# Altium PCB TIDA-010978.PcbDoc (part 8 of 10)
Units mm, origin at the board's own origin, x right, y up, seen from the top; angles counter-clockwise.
Board outline 243.95 x 94.85 mm, 4 copper layers (Top Layer, Mid Layer 1, Mid Layer 2, Bottom Layer), stack 1.623 mm thick; 865 components, 374 nets, 2308 pads, 2132 vias.
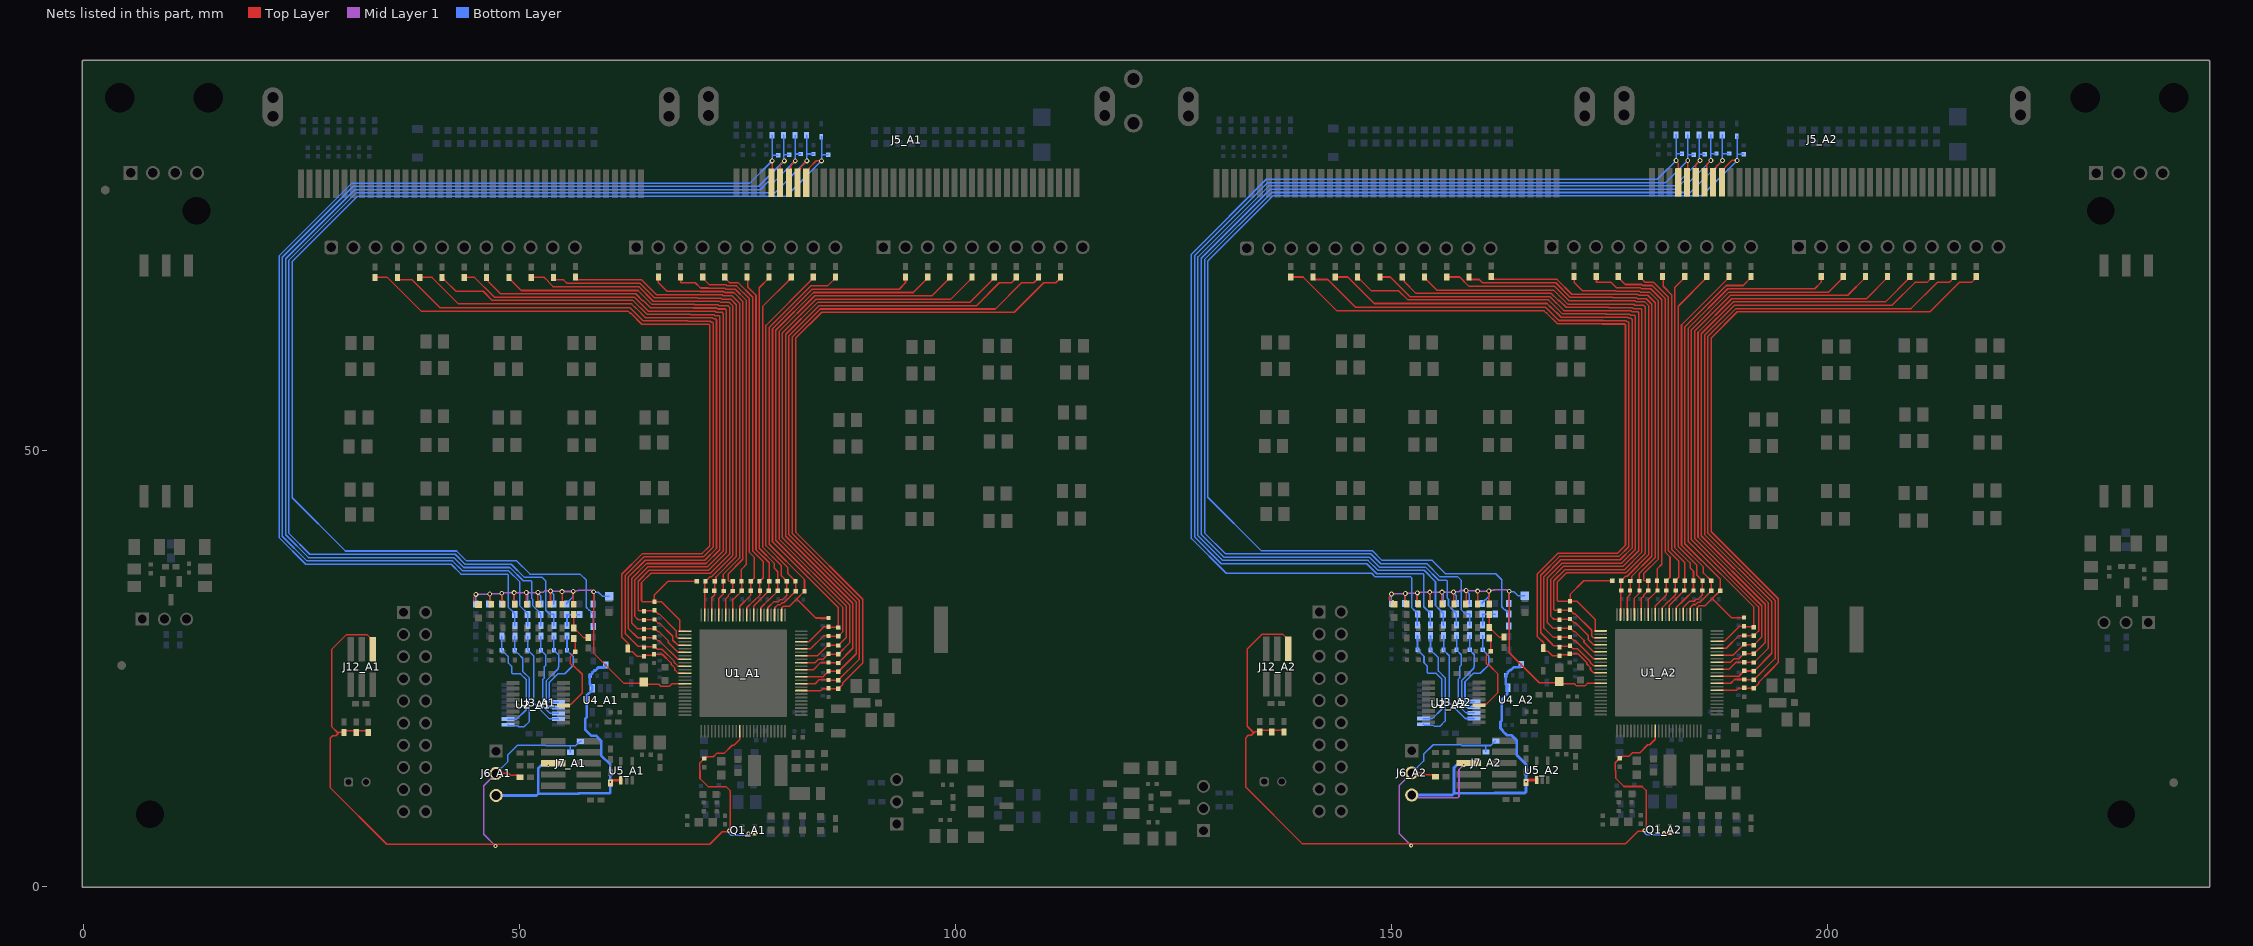
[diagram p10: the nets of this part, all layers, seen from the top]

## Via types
v1: diameter 0.559, hole 0.305, Top Layer to Bottom Layer, tented both sides, 1735 vias
v2: diameter 0.47, hole 0.2, Top Layer to Bottom Layer, tented both sides, 269 vias
v3: diameter 0.5, hole 0.2, Top Layer to Bottom Layer, tented both sides, 128 vias

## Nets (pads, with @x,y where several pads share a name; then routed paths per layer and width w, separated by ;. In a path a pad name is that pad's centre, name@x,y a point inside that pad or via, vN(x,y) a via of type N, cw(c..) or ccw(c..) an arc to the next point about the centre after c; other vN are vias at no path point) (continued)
TS10_A2: C78_A2.2 J5_A2.2 R137_A2.1 R143_A2.2 R144_A2.1 | length 131.7
  Top Layer w0.178: v1(182.649,83.25) 182.649,83.147 182.892,82.904 J5_A2.2@182.892,80.737
  Bottom Layer w0.178: R143_A2.2@152.984,29.951 152.974,29.962 R137_A2.1@152.974,31.221 152.974,31.321 152.562,31.732 152.554,31.732 152.348,31.938 152.348,35.361 152.223,35.486 148.142,35.486 147.727,35.901 131.047,35.901 127.053,39.895 127.053,72.501 135.633,81.081 137.767,81.081 180.48,81.081 v1(182.649,83.25) 182.649,84.012 ; R144_A2.1@182.624,86.187 182.649,86.162 182.649,84.012 ; C78_A2.2@183.317,84.012 182.649,84.012
TS10_MUX_A1: C65_A1.1 R143_A1.1 U2_A1.2 | length 12.7
  Bottom Layer w0.178: R143_A1.1@47.984,28.701 47.984,27.165 C65_A1.1@47.984,27.065 48.395,26.654 48.404,26.654 48.731,26.327 48.731,25.603 49.1,25.234 49.1,24.473 49.204,24.369 50.126,24.369 50.767,23.728 50.767,20.263 49.693,19.189 U2_A1.2@48.673,19.189
TS10_MUX_A2: C65_A2.1 R143_A2.1 U2_A2.2 | length 12.7
  Bottom Layer w0.178: R143_A2.1@152.984,28.751 152.984,27.215 C65_A2.1@152.984,27.115 153.395,26.704 153.404,26.704 153.731,26.377 153.731,25.653 154.1,25.284 154.1,24.523 154.204,24.419 155.126,24.419 155.767,23.778 155.767,20.313 154.693,19.239 U2_A2.2@153.673,19.239
TS11_A1: C84_A1.2 J5_A1.23 R135_A1.1 R149_A1.2 R150_A1.1 | length 133.7
  Top Layer w0.178: J5_A1.23@78.892,80.687 78.976,80.771 v1(78.976,83.2)
  Bottom Layer w0.178: R149_A1.2@49.477,29.901 49.462,29.917 R135_A1.1@49.462,31.171 49.462,31.271 49.051,31.682 49.042,31.682 48.699,32.025 48.699,35.71 48.595,35.814 43.299,35.814 42.165,36.947 25.486,36.947 22.431,40.002 22.431,72.295 30.79,80.654 32.767,80.654 76.429,80.654 v1(78.976,83.2) 78.976,83.862 ; R150_A1.1@78.951,86.137 78.976,86.112 78.976,83.862 ; C84_A1.2@79.667,83.862 78.976,83.862
TS11_A2: C84_A2.2 J5_A2.23 R135_A2.1 R149_A2.2 R150_A2.1 | length 133.7
  Top Layer w0.178: J5_A2.23@183.892,80.737 183.976,80.821 v1(183.976,83.25)
  Bottom Layer w0.178: R149_A2.2@154.477,29.951 154.462,29.967 R135_A2.1@154.462,31.221 154.462,31.321 154.051,31.732 154.042,31.732 153.699,32.075 153.699,35.76 153.595,35.864 148.299,35.864 147.165,36.997 130.486,36.997 127.431,40.052 127.431,72.345 135.79,80.704 137.767,80.704 181.429,80.704 v1(183.976,83.25) 183.976,83.912 ; R150_A2.1@183.951,86.187 183.976,86.162 183.976,83.912 ; C84_A2.2@184.667,83.912 183.976,83.912
TS11_MUX_A1: C63_A1.1 R149_A1.1 U2_A1.1 | length 13.3
  Bottom Layer w0.178: U2_A1.1@48.673,18.539 48.799,18.413 49.815,18.413 49.931,18.297 50.525,18.297 51.145,18.917 51.145,23.884 50.382,24.647 50.382,26.169 49.897,26.654 49.889,26.654 C63_A1.1@49.477,27.065 49.477,27.165 R149_A1.1@49.477,28.701
TS11_MUX_A2: C63_A2.1 R149_A2.1 U2_A2.1 | length 13.3
  Bottom Layer w0.178: U2_A2.1@153.673,18.589 153.799,18.463 154.815,18.463 154.931,18.347 155.525,18.347 156.145,18.967 156.145,23.934 155.382,24.697 155.382,26.219 154.897,26.704 154.889,26.704 C63_A2.1@154.477,27.115 154.477,27.215 R149_A2.1@154.477,28.751
TS12_A1: C86_A1.2 J5_A1.3 R133_A1.1 R156_A1.2 R157_A1.1 | length 135.2
  Top Layer w0.178: J5_A1.3@79.892,80.687 79.892,82.717 v1(80.376,83.2)
  Bottom Layer w0.178: R156_A1.2@50.971,29.901 50.95,29.922 R133_A1.1@50.95,31.171 50.95,31.271 50.539,31.682 50.53,31.682 50.051,32.162 50.051,34.893 48.752,36.192 43.455,36.192 42.322,37.325 25.642,37.325 22.809,40.158 22.809,72.138 30.946,80.276 32.767,80.276 77.451,80.276 v1(80.376,83.2) ; R157_A1.1@80.277,86.137 80.302,86.112 80.302,83.912 ; v1@80.303,83.201 80.303,83.912 C86_A1.2@80.942,83.912
TS12_A2: C86_A2.2 J5_A2.3 R133_A2.1 R156_A2.2 R157_A2.1 | length 135.2
  Top Layer w0.178: J5_A2.3@184.892,80.737 184.892,82.767 v1(185.376,83.25)
  Bottom Layer w0.178: R156_A2.2@155.971,29.951 155.95,29.972 R133_A2.1@155.95,31.221 155.95,31.321 155.539,31.732 155.53,31.732 155.051,32.212 155.051,34.943 153.752,36.242 148.455,36.242 147.322,37.375 130.642,37.375 127.809,40.208 127.809,72.188 135.946,80.326 137.767,80.326 182.451,80.326 v1(185.376,83.25) ; R157_A2.1@185.277,86.187 185.302,86.162 185.302,83.962 ; v1@185.303,83.251 185.303,83.962 C86_A2.2@185.942,83.962
TS12_MUX_A1: C61_A1.1 R156_A1.1 U2_A1.15 | length 11.6
  Bottom Layer w0.178: R156_A1.1@50.971,28.701 50.971,27.165 C61_A1.1@50.971,27.065 51.629,26.407 51.629,21.027 53.456,19.199 54.463,19.199 U2_A1.15@54.473,19.189
TS12_MUX_A2: C61_A2.1 R156_A2.1 U2_A2.15 | length 11.6
  Bottom Layer w0.178: R156_A2.1@155.971,28.751 155.971,27.215 C61_A2.1@155.971,27.115 156.629,26.457 156.629,21.077 158.456,19.249 159.463,19.249 U2_A2.15@159.473,19.239
TS13_A1: C89_A1.2 J5_A1.24 R132_A1.1 R159_A1.2 R160_A1.1 | length 137
  Top Layer w0.178: J5_A1.24@80.892,80.687 81.135,80.93 81.135,82.707 v1(81.629,83.2)
  Bottom Layer w0.178: R132_A1.1@52.438,31.171 52.438,29.927 R159_A1.2@52.464,29.901 ; R132_A1.1@52.438,31.271 52.027,31.682 52.018,31.682 51.539,32.162 51.539,32.891 51.402,33.027 51.402,34.951 51.298,35.055 50.423,35.055 48.908,36.569 43.612,36.569 42.478,37.703 25.799,37.703 23.187,40.315 23.187,71.982 31.103,79.898 32.767,79.898 77.608,79.898 78.483,80.773 79.201,80.773 v1(81.629,83.2) 81.629,83.987 ; R160_A1.1@81.603,86.137 81.629,86.112 81.629,83.987 ; C89_A1.2@82.267,83.987 81.629,83.987
TS13_A2: C89_A2.2 J5_A2.24 R132_A2.1 R159_A2.2 R160_A2.1 | length 137
  Top Layer w0.178: J5_A2.24@185.892,80.737 186.135,80.98 186.135,82.757 v1(186.629,83.25)
  Bottom Layer w0.178: R132_A2.1@157.438,31.221 157.438,29.977 R159_A2.2@157.464,29.951 ; R132_A2.1@157.438,31.321 157.027,31.732 157.018,31.732 156.539,32.212 156.539,32.941 156.402,33.077 156.402,35.001 156.298,35.105 155.423,35.105 153.908,36.619 148.612,36.619 147.478,37.753 130.799,37.753 128.187,40.365 128.187,72.032 136.103,79.948 137.767,79.948 182.608,79.948 183.483,80.823 184.201,80.823 v1(186.629,83.25) 186.629,84.037 ; R160_A2.1@186.603,86.187 186.629,86.162 186.629,84.037 ; C89_A2.2@187.267,84.037 186.629,84.037
TS13_MUX_A1: C60_A1.1 R159_A1.1 U2_A1.14 | length 10.5
  Bottom Layer w0.178: R159_A1.1@52.464,28.701 52.464,27.165 C60_A1.1@52.464,27.065 53.003,26.526 53.003,25.337 52.842,25.176 52.842,23.881 52.678,23.718 52.678,20.699 53.538,19.839 U2_A1.14@54.473,19.839
TS13_MUX_A2: C60_A2.1 R159_A2.1 U2_A2.14 | length 10.5
  Bottom Layer w0.178: R159_A2.1@157.464,28.751 157.464,27.215 C60_A2.1@157.464,27.115 158.003,26.576 158.003,25.387 157.842,25.226 157.842,23.931 157.678,23.768 157.678,20.749 158.538,19.889 U2_A2.14@159.473,19.889
TS14_A1: C92_A1.2 J5_A1.4 R131_A1.1 R163_A1.2 R164_A1.1 | length 139.7
  Top Layer w0.178: J5_A1.4@81.892,80.687 81.892,81.987 82.253,82.348 82.253,82.499 v1(82.955,83.2)
  Bottom Layer w0.178: R163_A1.2@53.958,29.901 53.958,31.113 54.015,31.171 R131_A1.1@53.926,31.171 53.878,31.219 53.463,31.219 53.027,31.656 53.027,33.61 52.993,33.643 52.993,34.114 53.027,34.147 53.027,35.029 52.623,35.433 50.579,35.433 49.065,36.947 43.768,36.947 42.635,38.081 25.955,38.081 23.565,40.471 23.565,71.826 31.259,79.52 79.275,79.52 v1(82.955,83.2) 82.955,83.987 ; R164_A1.1@82.93,86.137 82.955,86.112 82.955,83.987 ; C92_A1.2@83.717,83.987 82.955,83.987
TS14_A2: C92_A2.2 J5_A2.4 R131_A2.1 R163_A2.2 R164_A2.1 | length 139.7
  Top Layer w0.178: J5_A2.4@186.892,80.737 186.892,82.037 187.253,82.398 187.253,82.549 v1(187.955,83.25)
  Bottom Layer w0.178: R163_A2.2@158.958,29.951 158.958,31.163 159.015,31.221 R131_A2.1@158.926,31.221 158.878,31.269 158.463,31.269 158.027,31.706 158.027,33.66 157.993,33.693 157.993,34.164 158.027,34.197 158.027,35.079 157.623,35.483 155.579,35.483 154.065,36.997 148.768,36.997 147.635,38.131 130.955,38.131 128.565,40.521 128.565,71.876 136.259,79.57 184.275,79.57 v1(187.955,83.25) 187.955,84.037 ; R164_A2.1@187.93,86.187 187.955,86.162 187.955,84.037 ; C92_A2.2@188.717,84.037 187.955,84.037
TS14_MUX_A1: C59_A1.1 R163_A1.1 U2_A1.13 | length 10.2
  Bottom Layer w0.178: R163_A1.1@53.958,28.701 53.958,27.165 C59_A1.1@53.957,27.065 54.496,26.526 54.496,25.169 54.447,25.12 54.447,24.952 53.056,23.561 53.056,20.971 53.538,20.489 U2_A1.13@54.473,20.489
TS14_MUX_A2: C59_A2.1 R163_A2.1 U2_A2.13 | length 10.2
  Bottom Layer w0.178: R163_A2.1@158.958,28.751 158.958,27.215 C59_A2.1@158.957,27.115 159.496,26.576 159.496,25.219 159.447,25.17 159.447,25.002 158.056,23.611 158.056,21.021 158.538,20.539 U2_A2.13@159.473,20.539
TS15_A1: C118_A1.2 J5_A1.25 R193_A1.1 R196_A1.2 RT1_A1.1 | length 143
  Top Layer w0.178: J5_A1.25@82.892,80.687 82.892,81.987 83.253,82.348 83.253,82.428 84.026,83.2 v1(84.642,83.2)
  Bottom Layer w0.178: R196_A1.2@58.452,29.784 58.452,31.165 R193_A1.1@58.446,31.171 58.446,31.271 58.035,31.682 57.97,31.682 57.646,32.006 57.646,35.12 56.955,35.811 51.197,35.811 49.683,37.325 43.925,37.325 42.791,38.458 30.05,38.458 23.942,44.566 23.942,71.669 31.416,79.142 80.584,79.142 v1(84.642,83.2) 84.642,83.912 ; RT1_A1.1@84.617,85.972 84.642,85.947 84.642,83.912 ; C118_A1.2@85.392,83.912 84.642,83.912
TS15_A2: C118_A2.2 J5_A2.25 R193_A2.1 R196_A2.2 RT1_A2.1 | length 143
  Top Layer w0.178: J5_A2.25@187.892,80.737 187.892,82.037 188.253,82.398 188.253,82.478 189.026,83.25 v1(189.642,83.25)
  Bottom Layer w0.178: R196_A2.2@163.452,29.834 163.452,31.215 R193_A2.1@163.446,31.221 163.446,31.321 163.035,31.732 162.97,31.732 162.646,32.056 162.646,35.17 161.955,35.861 156.197,35.861 154.683,37.375 148.925,37.375 147.791,38.508 135.05,38.508 128.942,44.616 128.942,71.719 136.416,79.192 185.584,79.192 v1(189.642,83.25) 189.642,83.962 ; RT1_A2.1@189.617,86.022 189.642,85.997 189.642,83.962 ; C118_A2.2@190.392,83.962 189.642,83.962
TS_R1_A1: R171_A1.1 R184_A1.2 R185_A1.2 | length 3.7
  Top Layer w0.178: R171_A1.1@56.218,31.153 R184_A1.2@56.218,29.651 56.218,29.551 56.429,29.34 56.529,29.34 57.335,28.534 R185_A1.2@57.902,28.534
TS_R1_A2: R171_A2.1 R184_A2.2 R185_A2.2 | length 3.7
  Top Layer w0.178: R171_A2.1@161.218,31.203 R184_A2.2@161.218,29.701 161.218,29.601 161.429,29.39 161.529,29.39 162.335,28.584 R185_A2.2@162.902,28.584
TS_R1MUX_A1: C73_A1.1 R184_A1.1 U3_A1.12 | length 10
  Top Layer w0.178: U3_A1.12@55.043,20.724 55.179,20.86 55.884,20.86 57.202,22.178 57.202,24.319 56.207,25.314 56.058,25.314 55.849,25.524 55.849,26.355 C73_A1.1@56.387,26.893 56.387,28.282 R184_A1.1@56.218,28.451
TS_R1MUX_A2: C73_A2.1 R184_A2.1 U3_A2.12 | length 10
  Top Layer w0.178: U3_A2.12@160.043,20.774 160.179,20.91 160.884,20.91 162.202,22.228 162.202,24.369 161.207,25.364 161.058,25.364 160.849,25.574 160.849,26.405 C73_A2.1@161.387,26.943 161.387,28.332 R184_A2.1@161.218,28.501
TS_R2_A1: R134_A1.1 R152_A1.2 R153_A1.2 | length 2.8
  Bottom Layer w0.178: R152_A1.2@55.451,29.901 55.451,31.134 R134_A1.1@55.414,31.171 R153_A1.2@56.902,31.171
TS_R2_A2: R134_A2.1 R152_A2.2 R153_A2.2 | length 2.8
  Bottom Layer w0.178: R152_A2.2@160.451,29.951 160.451,31.184 R134_A2.1@160.414,31.221 R153_A2.2@161.902,31.221
TS_R2MUX_A1: C62_A1.1 R152_A1.1 U2_A1.12 | length 10.4
  Bottom Layer w0.178: U2_A1.12@54.473,21.139 53.538,21.139 53.434,21.243 53.434,23.405 54.408,24.379 55.188,24.379 56.175,25.366 56.175,26.349 55.871,26.654 55.862,26.654 C62_A1.1@55.451,27.065 55.451,27.165 R152_A1.1@55.451,28.701
TS_R2MUX_A2: C62_A2.1 R152_A2.1 U2_A2.12 | length 10.4
  Bottom Layer w0.178: U2_A2.12@159.473,21.189 158.538,21.189 158.434,21.293 158.434,23.455 159.408,24.429 160.188,24.429 161.175,25.416 161.175,26.399 160.871,26.704 160.862,26.704 C62_A2.1@160.451,27.115 160.451,27.215 R152_A2.1@160.451,28.751
TSREF_A1: C23_A1.2 C24_A1.2 R127_A1.1 R131_A1.2 R132_A1.2 R133_A1.2 R134_A1.2 R135_A1.2 R136_A1.2 R137_A1.2 R138_A1.2 R168_A1.2 R169_A1.2 R170_A1.2 R171_A1.2 R172_A1.2 R173_A1.2 R174_A1.2 R175_A1.2 R193_A1.2 U1_A1.66 | length 60.4
  Top Layer w0.178: v1(44.997,33.484) 44.997,33.381 44.733,33.117 44.733,32.865 45.246,32.353 C24_A1.2@45.296,32.353 ; v1(46.599,33.531) 46.599,32.513 R173_A1.2@46.759,32.353 ; v1(47.974,33.609) 47.974,32.489 R175_A1.2@48.11,32.353 ; v1(49.39,33.689) 49.39,32.424 R174_A1.2@49.462,32.353 ; v1(50.787,33.696) 50.787,32.379 R172_A1.2@50.813,32.353 ; v1(52.119,33.714) 52.119,32.398 R170_A1.2@52.164,32.353 ; R169_A1.2@53.515,32.353 53.562,32.399 v1(53.562,33.879) ; R168_A1.2@54.867,32.353 54.883,32.369 v1(54.883,33.804) ; v1(56.175,33.829) 56.175,32.396 R171_A1.2@56.218,32.353 ; v1(58.502,33.788) 58.502,26.755 61.943,23.314 64.124,23.314 C23_A1.2@64.246,23.436 64.488,23.194 65.961,23.194 66.215,22.94 67.193,22.94 67.49,23.237 68.971,23.237 U1_A1.66@68.982,23.249
  Mid Layer 1 w0.178: v1(44.997,33.484) 45.021,33.508 46.575,33.508 46.638,33.57 47.935,33.57 v1(47.974,33.609) 48.026,33.661 52.066,33.661 v1(52.119,33.714) 52.722,33.714 52.886,33.879 v1(53.562,33.879) 53.599,33.841 54.846,33.841 v1(54.883,33.804) 54.896,33.817 v1@56.162,33.817 ; v1@56.229,33.883 56.721,33.883 56.794,33.956 58.23,33.956 58.398,33.788 v1(58.502,33.788)
  Bottom Layer w0.178: v1(44.997,33.484) 44.997,32.402 R136_A1.2@45.066,32.333 ; R138_A1.2@46.486,32.371 46.599,32.484 v1(46.599,33.531) ; R137_A1.2@47.974,32.371 v1(47.974,33.609) ; v1(49.39,33.689) 49.39,32.442 R135_A1.2@49.462,32.371 ; v1(50.787,33.696) 50.787,33.593 50.95,33.43 R133_A1.2@50.95,32.371 ; v1(52.119,33.714) 52.119,33.611 52.438,33.292 R132_A1.2@52.438,32.371 ; v1(53.562,33.879) 53.562,33.834 53.926,33.47 R131_A1.2@53.926,32.371 ; R134_A1.2@55.414,32.371 55.414,32.471 56.175,33.232 v1(56.175,33.829) ; R193_A1.2@58.446,32.371 58.502,32.427 v1(58.502,33.788) 58.552,33.737 59.048,33.737 59.514,33.271 R127_A1.1@60.292,33.271
TSREF_A2: C23_A2.2 C24_A2.2 R127_A2.1 R131_A2.2 R132_A2.2 R133_A2.2 R134_A2.2 R135_A2.2 R136_A2.2 R137_A2.2 R138_A2.2 R168_A2.2 R169_A2.2 R170_A2.2 R171_A2.2 R172_A2.2 R173_A2.2 R174_A2.2 R175_A2.2 R193_A2.2 U1_A2.66 | length 60.4
  Top Layer w0.178: v1(149.997,33.534) 149.997,33.431 149.733,33.167 149.733,32.915 150.246,32.403 C24_A2.2@150.296,32.403 ; v1(151.599,33.581) 151.599,32.563 R173_A2.2@151.759,32.403 ; v1(152.974,33.659) 152.974,32.539 R175_A2.2@153.11,32.403 ; v1(154.39,33.739) 154.39,32.474 R174_A2.2@154.462,32.403 ; v1(155.787,33.746) 155.787,32.429 R172_A2.2@155.813,32.403 ; v1(157.119,33.764) 157.119,32.448 R170_A2.2@157.164,32.403 ; R169_A2.2@158.515,32.403 158.562,32.449 v1(158.562,33.929) ; R168_A2.2@159.867,32.403 159.883,32.419 v1(159.883,33.854) ; v1(161.175,33.879) 161.175,32.446 R171_A2.2@161.218,32.403 ; v1(163.502,33.838) 163.502,26.805 166.943,23.364 169.124,23.364 C23_A2.2@169.246,23.486 169.488,23.244 170.961,23.244 171.215,22.99 172.193,22.99 172.49,23.287 173.971,23.287 U1_A2.66@173.982,23.299
  Mid Layer 1 w0.178: v1(149.997,33.534) 150.021,33.558 151.575,33.558 151.638,33.62 152.935,33.62 v1(152.974,33.659) 153.026,33.711 157.066,33.711 v1(157.119,33.764) 157.722,33.764 157.886,33.929 v1(158.562,33.929) 158.599,33.891 159.846,33.891 v1(159.883,33.854) 159.896,33.867 v1@161.162,33.867 ; v1@161.229,33.933 161.721,33.933 161.794,34.006 163.23,34.006 163.398,33.838 v1(163.502,33.838)
  Bottom Layer w0.178: v1(149.997,33.534) 149.997,32.452 R136_A2.2@150.066,32.383 ; R138_A2.2@151.486,32.421 151.599,32.534 v1(151.599,33.581) ; R137_A2.2@152.974,32.421 v1(152.974,33.659) ; v1(154.39,33.739) 154.39,32.492 R135_A2.2@154.462,32.421 ; v1(155.787,33.746) 155.787,33.643 155.95,33.48 R133_A2.2@155.95,32.421 ; v1(157.119,33.764) 157.119,33.661 157.438,33.342 R132_A2.2@157.438,32.421 ; v1(158.562,33.929) 158.562,33.884 158.926,33.52 R131_A2.2@158.926,32.421 ; R134_A2.2@160.414,32.421 160.414,32.521 161.175,33.282 v1(161.175,33.879) ; R193_A2.2@163.446,32.421 163.502,32.477 v1(163.502,33.838) 163.552,33.787 164.048,33.787 164.514,33.321 R127_A2.1@165.292,33.321
VC0_A1: C162_A1.1 C164_A1.2 D8_A1.1 R231_A1.2 U1_A1.63 | length 94.4
  Top Layer w0.178: R231_A1.2@33.445,69.832 34.858,69.832 38.753,65.937 62.492,65.937 62.717,65.712 62.789,65.712 64.037,64.464 69.132,64.464 69.157,64.439 71.734,64.439 71.838,64.335 71.838,39.067 70.931,38.161 64.111,38.161 61.73,35.78 61.73,28.612 62.457,27.886 62.457,27.309 D8_A1.1@62.422,27.274 62.422,27.087 62.583,26.926 62.938,26.926 63.474,26.39 C162_A1.1@64.275,26.39 ; C162_A1.1@64.365,26.481 64.391,26.506 65.321,26.506 C164_A1.2@65.437,26.623 66.389,26.623 67.393,25.618 67.393,25.47 67.823,25.04 67.823,24.803 68.167,24.46 68.971,24.46 U1_A1.63@68.982,24.449
VC0_A2: C162_A2.1 C164_A2.2 D8_A2.1 R231_A2.2 U1_A2.63 | length 94.4
  Top Layer w0.178: R231_A2.2@138.445,69.882 139.858,69.882 143.753,65.987 167.492,65.987 167.717,65.762 167.789,65.762 169.037,64.514 174.132,64.514 174.157,64.489 176.734,64.489 176.838,64.385 176.838,39.117 175.931,38.211 169.111,38.211 166.73,35.83 166.73,28.662 167.457,27.936 167.457,27.359 D8_A2.1@167.422,27.324 167.422,27.137 167.583,26.976 167.938,26.976 168.474,26.44 C162_A2.1@169.275,26.44 ; C162_A2.1@169.365,26.531 169.391,26.556 170.321,26.556 C164_A2.2@170.437,26.673 171.389,26.673 172.393,25.668 172.393,25.52 172.823,25.09 172.823,24.853 173.167,24.51 173.971,24.51 U1_A2.63@173.982,24.499
VC1_A1: C156_A1.1 C162_A1.2 R229_A1.2 U1_A1.61 | length 91.1
  Top Layer w0.178: R229_A1.2@36.003,69.832 36.003,69.732 36.189,69.546 37.702,69.546 40.882,66.366 62.67,66.366 64.194,64.842 69.289,64.842 69.314,64.817 71.89,64.817 72.004,64.703 72.111,64.703 72.216,64.599 72.216,38.91 71.088,37.783 64.267,37.783 62.108,35.624 62.108,29.028 62.738,28.399 62.745,28.399 63.374,27.77 63.374,27.762 63.587,27.55 64.115,27.55 C162_A1.2@64.275,27.39 64.356,27.472 C156_A1.1@65.398,27.472 ; U1_A1.61@68.982,25.249 68.971,25.26 68.167,25.26 67.771,25.656 67.771,25.775 66.369,27.177 65.856,27.177 C156_A1.1@65.48,27.554 ; C156_A1.1@65.398,27.472 C156_A1.1@65.48,27.554 ; C156_A1.1@65.398,27.472 C156_A1.1@65.48,27.554 ; C156_A1.1@65.398,27.472 C156_A1.1@65.48,27.554
VC1_A2: C156_A2.1 C162_A2.2 R229_A2.2 U1_A2.61 | length 91.1
  Top Layer w0.178: R229_A2.2@141.003,69.882 141.003,69.782 141.189,69.596 142.702,69.596 145.882,66.416 167.67,66.416 169.194,64.892 174.289,64.892 174.314,64.867 176.89,64.867 177.004,64.753 177.111,64.753 177.216,64.649 177.216,38.96 176.088,37.833 169.267,37.833 167.108,35.674 167.108,29.078 167.738,28.449 167.745,28.449 168.374,27.82 168.374,27.812 168.587,27.6 169.115,27.6 C162_A2.2@169.275,27.44 169.356,27.522 C156_A2.1@170.398,27.522 ; U1_A2.61@173.982,25.299 173.971,25.31 173.167,25.31 172.771,25.706 172.771,25.825 171.369,27.227 170.856,27.227 C156_A2.1@170.48,27.604 ; C156_A2.1@170.398,27.522 C156_A2.1@170.48,27.604 ; C156_A2.1@170.398,27.522 C156_A2.1@170.48,27.604 ; C156_A2.1@170.398,27.522 C156_A2.1@170.48,27.604
VC2_A1: C152_A1.1 C156_A1.2 R223_A1.2 U1_A1.59 | length 87.6
  Top Layer w0.178: R223_A1.2@38.56,69.832 39.974,69.832 43.011,66.794 62.847,66.794 63.323,66.318 63.359,66.318 64.458,65.22 69.445,65.22 69.47,65.195 72.151,65.195 72.265,65.081 72.489,65.081 72.593,64.977 72.593,38.754 71.244,37.405 64.424,37.405 62.486,35.467 62.486,29.582 63.569,28.499 64.305,28.499 64.317,28.511 65.437,28.511 C156_A1.2@65.48,28.554 65.889,28.144 66.073,28.144 68.168,26.049 U1_A1.59@68.982,26.049
VC2_A2: C152_A2.1 C156_A2.2 R223_A2.2 U1_A2.59 | length 87.6
  Top Layer w0.178: R223_A2.2@143.56,69.882 144.974,69.882 148.011,66.844 167.847,66.844 168.323,66.368 168.359,66.368 169.458,65.27 174.445,65.27 174.47,65.245 177.151,65.245 177.265,65.131 177.489,65.131 177.593,65.027 177.593,38.804 176.244,37.455 169.424,37.455 167.486,35.517 167.486,29.632 168.569,28.549 169.305,28.549 169.317,28.561 170.437,28.561 C156_A2.2@170.48,28.604 170.889,28.194 171.073,28.194 173.168,26.099 U1_A2.59@173.982,26.099
VC3_A1: C144_A1.1 C152_A1.2 R219_A1.2 U1_A1.57 | length 84.8
  Top Layer w0.178: R219_A1.2@41.118,69.832 41.118,69.732 41.304,69.546 41.404,69.546 42.713,68.237 45.843,68.237 46.883,67.197 63.014,67.197 64.614,65.597 69.602,65.597 69.627,65.572 72.307,65.572 72.421,65.459 72.867,65.459 72.971,65.354 72.971,38.597 71.401,37.027 64.58,37.027 62.864,35.311 62.864,30.205 63.531,29.538 65.41,29.538 C144_A1.1@65.48,29.607 65.912,29.174 66.05,29.174 67.08,28.144 67.08,27.946 68.167,26.86 68.971,26.86 U1_A1.57@68.982,26.849
VC3_A2: C144_A2.1 C152_A2.2 R219_A2.2 U1_A2.57 | length 84.8
  Top Layer w0.178: R219_A2.2@146.118,69.882 146.118,69.782 146.304,69.596 146.404,69.596 147.713,68.287 150.843,68.287 151.883,67.247 168.014,67.247 169.614,65.647 174.602,65.647 174.627,65.622 177.307,65.622 177.421,65.509 177.867,65.509 177.971,65.404 177.971,38.647 176.401,37.077 169.58,37.077 167.864,35.361 167.864,30.255 168.531,29.588 170.41,29.588 C144_A2.1@170.48,29.657 170.912,29.224 171.05,29.224 172.08,28.194 172.08,27.996 173.167,26.91 173.971,26.91 U1_A2.57@173.982,26.899
VC4_A1: C136_A1.1 C144_A1.2 R216_A1.2 U1_A1.55 | length 81.7
  Top Layer w0.178: R216_A1.2@43.676,69.832 44.854,69.832 47.111,67.575 63.171,67.575 64.771,65.975 69.758,65.975 69.783,65.95 72.464,65.95 72.578,65.836 73.245,65.836 73.349,65.732 73.349,38.441 71.557,36.649 64.737,36.649 63.242,35.154 63.242,30.952 63.617,30.577 65.449,30.577 C144_A1.2@65.48,30.607 65.89,30.197 66.072,30.197 67.59,28.678 67.59,28.236 68.167,27.66 68.971,27.66 U1_A1.55@68.982,27.649
VC4_A2: C136_A2.1 C144_A2.2 R216_A2.2 U1_A2.55 | length 81.7
  Top Layer w0.178: R216_A2.2@148.676,69.882 149.854,69.882 152.111,67.625 168.171,67.625 169.771,66.025 174.758,66.025 174.783,66 177.464,66 177.578,65.886 178.245,65.886 178.349,65.782 178.349,38.491 176.557,36.699 169.737,36.699 168.242,35.204 168.242,31.002 168.617,30.627 170.449,30.627 C144_A2.2@170.48,30.657 170.89,30.247 171.072,30.247 172.59,28.728 172.59,28.286 173.167,27.71 173.971,27.71 U1_A2.55@173.982,27.699
VC5_A1: C130_A1.1 C136_A1.2 R213_A1.2 U1_A1.53 | length 78.9
  Top Layer w0.178: R213_A1.2@46.233,69.832 46.444,69.621 46.444,69.333 47.824,67.953 63.327,67.953 64.143,67.138 64.252,67.138 65.037,66.353 69.915,66.353 69.94,66.328 72.62,66.328 72.734,66.214 73.623,66.214 73.727,66.11 73.727,38.284 71.714,36.272 64.893,36.272 63.619,34.998 63.619,31.707 63.724,31.603 65.423,31.603 C130_A1.1@65.48,31.66 65.912,31.228 66.05,31.228 67.957,29.32 67.957,29.048 67.968,29.038 67.968,28.658 68.167,28.46 68.971,28.46 U1_A1.53@68.982,28.449
VC5_A2: C130_A2.1 C136_A2.2 R213_A2.2 U1_A2.53 | length 78.9
  Top Layer w0.178: R213_A2.2@151.233,69.882 151.444,69.671 151.444,69.383 152.824,68.003 168.327,68.003 169.143,67.188 169.252,67.188 170.037,66.403 174.915,66.403 174.94,66.378 177.62,66.378 177.734,66.264 178.623,66.264 178.727,66.16 178.727,38.334 176.714,36.322 169.893,36.322 168.619,35.048 168.619,31.757 168.724,31.653 170.423,31.653 C130_A2.1@170.48,31.71 170.912,31.278 171.05,31.278 172.957,29.37 172.957,29.098 172.968,29.088 172.968,28.708 173.167,28.51 173.971,28.51 U1_A2.53@173.982,28.499
VC6_A1: C126_A1.1 C130_A1.2 R207_A1.2 U1_A1.51 | length 82.1
  Top Layer w0.178: R207_A1.2@48.791,69.832 48.791,69.732 50.192,68.331 63.593,68.331 65.193,66.731 70.071,66.731 70.096,66.706 72.777,66.706 72.891,66.592 73.91,66.592 74.105,66.397 74.105,38.128 71.87,35.894 65.05,35.894 63.997,34.841 63.997,32.764 64.101,32.66 C130_A1.2@65.48,32.66 ; U1_A1.51@68.982,29.249 68.381,29.249 68.37,29.26 68.37,30.562 66.271,32.66 C130_A1.2@65.48,32.66 ; C126_A1.1@70.333,34.999 67.048,34.999 65.48,33.431 C130_A1.2@65.48,32.66
VC6_A2: C126_A2.1 C130_A2.2 R207_A2.2 U1_A2.51 | length 82.1
  Top Layer w0.178: R207_A2.2@153.791,69.882 153.791,69.782 155.192,68.381 168.593,68.381 170.193,66.781 175.071,66.781 175.096,66.756 177.777,66.756 177.891,66.642 178.91,66.642 179.105,66.447 179.105,38.178 176.87,35.944 170.05,35.944 168.997,34.891 168.997,32.814 169.101,32.71 C130_A2.2@170.48,32.71 ; U1_A2.51@173.982,29.299 173.381,29.299 173.37,29.31 173.37,30.612 171.271,32.71 C130_A2.2@170.48,32.71 ; C126_A2.1@175.333,35.049 172.048,35.049 170.48,33.481 C130_A2.2@170.48,32.71
VC7_A1: C120_A1.1 C126_A1.2 R205_A1.2 U1_A1.49 | length 61.4
  Top Layer w0.178: R205_A1.2@51.348,69.832 52.842,69.832 53.317,69.357 53.317,69.312 53.843,68.786 63.672,68.786 65.35,67.109 70.228,67.109 70.253,67.084 72.933,67.084 73.047,66.97 74.066,66.97 74.482,66.553 74.482,37.971 72.027,35.516 71.85,35.516 C126_A1.2@71.333,34.999 71.268,34.934 71.268,31.135 U1_A1.49@71.257,31.124
VC7_A2: C120_A2.1 C126_A2.2 R205_A2.2 U1_A2.49 | length 61.4
  Top Layer w0.178: R205_A2.2@156.348,69.882 157.842,69.882 158.317,69.407 158.317,69.362 158.843,68.836 168.672,68.836 170.35,67.159 175.228,67.159 175.253,67.134 177.933,67.134 178.047,67.02 179.066,67.02 179.482,66.603 179.482,38.021 177.027,35.566 176.85,35.566 C126_A2.2@176.333,35.049 176.268,34.984 176.268,31.185 U1_A2.49@176.257,31.174
VC8_A1: C116_A1.1 C120_A1.2 R203_A1.2 U1_A1.47 | length 59.1
  Top Layer w0.178: R203_A1.2@53.906,69.832 53.906,69.732 54.091,69.546 55.058,69.546 55.441,69.164 63.829,69.164 65.506,67.486 70.384,67.486 70.409,67.461 73.09,67.461 73.204,67.348 74.223,67.348 74.86,66.71 74.86,37.815 72.536,35.491 72.536,35.117 C116_A1.1@72.394,34.974 72.394,33.449 72.057,33.112 U1_A1.47@72.057,31.124
VC8_A2: C116_A2.1 C120_A2.2 R203_A2.2 U1_A2.47 | length 59.1
  Top Layer w0.178: R203_A2.2@158.906,69.882 158.906,69.782 159.091,69.596 160.058,69.596 160.441,69.214 168.829,69.214 170.506,67.536 175.384,67.536 175.409,67.511 178.09,67.511 178.204,67.398 179.223,67.398 179.86,66.76 179.86,37.865 177.536,35.541 177.536,35.167 C116_A2.1@177.394,35.024 177.394,33.499 177.057,33.162 U1_A2.47@177.057,31.174
VC9_A1: C110_A1.1 C116_A1.2 R201_A1.2 U1_A1.45 | length 56.8
  Top Layer w0.178: R201_A1.2@56.438,69.867 56.438,69.767 56.649,69.556 63.991,69.556 65.683,67.864 70.541,67.864 70.566,67.839 73.246,67.839 73.36,67.725 74.379,67.725 75.238,66.866 75.238,37.658 73.394,35.815 C116_A1.2@73.394,34.974 73.394,33.549 72.857,33.012 U1_A1.45@72.857,31.124
VC9_A2: C110_A2.1 C116_A2.2 R201_A2.2 U1_A2.45 | length 56.8
  Top Layer w0.178: R201_A2.2@161.438,69.917 161.438,69.817 161.649,69.606 168.991,69.606 170.683,67.914 175.541,67.914 175.566,67.889 178.246,67.889 178.36,67.775 179.379,67.775 180.238,66.916 180.238,37.708 178.394,35.865 C116_A2.2@178.394,35.024 178.394,33.599 177.857,33.062 U1_A2.45@177.857,31.174
VC10_A1: C106_A1.1 C110_A1.2 R199_A1.2 U1_A1.43 | length 48.7
  Top Layer w0.178: R199_A1.2@65.936,69.867 65.936,69.217 66.911,68.242 70.697,68.242 70.722,68.217 73.403,68.217 73.517,68.103 74.59,68.103 75.616,67.078 75.616,37.502 73.933,35.819 73.933,35.083 74.037,34.979 C106_A1.1@74.456,34.979 74.472,34.963 74.472,33.904 C110_A1.2@74.447,33.879 73.922,33.353 73.922,33.229 73.657,32.964 U1_A1.43@73.657,31.124
VC10_A2: C106_A2.1 C110_A2.2 R199_A2.2 U1_A2.43 | length 48.7
  Top Layer w0.178: R199_A2.2@170.936,69.917 170.936,69.267 171.911,68.292 175.697,68.292 175.722,68.267 178.403,68.267 178.517,68.153 179.59,68.153 180.616,67.128 180.616,37.552 178.933,35.869 178.933,35.133 179.037,35.029 C106_A2.1@179.456,35.029 179.472,35.013 179.472,33.954 C110_A2.2@179.447,33.929 178.922,33.403 178.922,33.279 178.657,33.014 U1_A2.43@178.657,31.174
VC11_A1: C100_A1.1 C106_A1.2 R197_A1.2 U1_A1.41 | length 46.2
  Top Layer w0.178: R197_A1.2@68.512,69.953 68.512,69.217 70.168,69.217 70.765,68.62 71.624,68.62 71.648,68.595 73.559,68.595 73.673,68.481 74.747,68.481 75.994,67.234 75.994,36.88 75.456,36.342 C106_A1.2@75.456,34.979 75.483,34.952 75.483,33.913 C100_A1.1@75.51,33.886 74.752,33.128 74.722,33.128 74.457,32.864 U1_A1.41@74.457,31.124 74.457,30.826 U1_A1.41@74.468,30.815
VC11_A2: C100_A2.1 C106_A2.2 R197_A2.2 U1_A2.41 | length 46.2
  Top Layer w0.178: R197_A2.2@173.512,70.003 173.512,69.267 175.168,69.267 175.765,68.67 176.624,68.67 176.648,68.645 178.559,68.645 178.673,68.531 179.747,68.531 180.994,67.284 180.994,36.93 180.456,36.392 C106_A2.2@180.456,35.029 180.483,35.002 180.483,33.963 C100_A2.1@180.51,33.936 179.752,33.178 179.722,33.178 179.457,32.914 U1_A2.41@179.457,31.174 179.457,30.876 U1_A2.41@179.468,30.865
VC12_A1: C97_A1.1 C100_A1.2 R194_A1.2 U1_A1.39 | length 43.7
  Top Layer w0.178: R194_A1.2@71.061,69.961 71.061,69.717 71.805,68.973 73.716,68.973 73.83,68.859 74.903,68.859 76.371,67.391 76.371,38.298 76.943,37.726 76.943,35.397 C97_A1.1@76.531,34.984 76.52,34.974 76.52,33.897 C100_A1.2@76.51,33.886 76.51,33.363 75.262,32.115 75.262,31.128 U1_A1.39@75.257,31.124
VC12_A2: C97_A2.1 C100_A2.2 R194_A2.2 U1_A2.39 | length 43.7
  Top Layer w0.178: R194_A2.2@176.061,70.011 176.061,69.767 176.805,69.023 178.716,69.023 178.83,68.909 179.903,68.909 181.371,67.441 181.371,38.348 181.943,37.776 181.943,35.447 C97_A2.1@181.531,35.034 181.52,35.024 181.52,33.947 C100_A2.2@181.51,33.936 181.51,33.413 180.262,32.165 180.262,31.178 U1_A2.39@180.257,31.174
VC13_A1: C91_A1.1 C97_A1.2 R192_A1.2 U1_A1.37 | length 42
  Top Layer w0.178: R192_A1.2@73.548,69.867 73.548,69.767 74.078,69.237 75.06,69.237 76.749,67.547 76.749,38.454 77.943,37.26 77.943,35.397 C97_A1.2@77.531,34.984 77.559,34.956 77.559,33.914 C91_A1.1@77.587,33.886 77.587,33.42 76.821,32.654 76.783,32.654 76.068,31.939 76.068,31.135 U1_A1.37@76.057,31.124
VC13_A2: C91_A2.1 C97_A2.2 R192_A2.2 U1_A2.37 | length 42
  Top Layer w0.178: R192_A2.2@178.548,69.917 178.548,69.817 179.078,69.287 180.06,69.287 181.749,67.597 181.749,38.504 182.943,37.31 182.943,35.447 C97_A2.2@182.531,35.034 182.559,35.006 182.559,33.964 C91_A2.1@182.587,33.936 182.587,33.47 181.821,32.704 181.783,32.704 181.068,31.989 181.068,31.185 U1_A2.37@181.057,31.174
VC14_A1: C91_A1.2 C163_A1.1 R232_A1.2 U1_A1.35 | length 40.6
  Top Layer w0.178: R232_A1.2@76.158,69.962 76.158,68.762 77.127,67.793 77.127,38.611 78.634,37.104 C163_A1.1@78.634,34.986 78.61,34.962 78.61,33.909 C91_A1.2@78.587,33.886 76.857,32.156 U1_A1.35@76.857,31.124
VC14_A2: C91_A2.2 C163_A2.1 R232_A2.2 U1_A2.35 | length 40.6
  Top Layer w0.178: R232_A2.2@181.158,70.012 181.158,68.812 182.127,67.843 182.127,38.661 183.634,37.154 C163_A2.1@183.634,35.036 183.61,35.012 183.61,33.959 C91_A2.2@183.587,33.936 181.857,32.206 U1_A2.35@181.857,31.174
VC15_A1: C157_A1.1 C163_A1.2 R230_A1.2 U1_A1.33 | length 40.9
  Top Layer w0.178: U1_A1.33@77.657,31.124 77.668,31.135 77.668,31.939 78.561,32.832 78.585,32.832 C157_A1.1@79.639,33.886 79.637,33.889 79.637,34.983 C163_A1.2@79.634,34.986 79.634,36.087 79.24,36.482 79.24,37.032 77.505,38.767 77.505,68.65 78.622,69.767 R230_A1.2@78.622,69.867
VC15_A2: C157_A2.1 C163_A2.2 R230_A2.2 U1_A2.33 | length 40.9
  Top Layer w0.178: U1_A2.33@182.657,31.174 182.668,31.185 182.668,31.989 183.561,32.882 183.585,32.882 C157_A2.1@184.639,33.936 184.637,33.939 184.637,35.033 C163_A2.2@184.634,35.036 184.634,36.137 184.24,36.532 184.24,37.082 182.505,38.817 182.505,68.7 183.622,69.817 R230_A2.2@183.622,69.917
VC16_A1: C153_A1.1 C157_A1.2 R224_A1.2 U1_A1.31 | length 42.6
  Top Layer w0.178: U1_A1.31@78.457,31.124 78.468,31.135 78.468,31.939 79.183,32.654 79.715,32.654 79.954,32.893 80.163,32.893 80.639,33.37 C157_A1.2@80.639,33.886 80.65,33.897 80.65,34.988 C153_A1.1@80.661,34.999 80.011,35.648 80.011,36.795 77.883,38.924 77.883,66.49 81.159,69.767 R224_A1.2@81.159,69.867
VC16_A2: C153_A2.1 C157_A2.2 R224_A2.2 U1_A2.31 | length 42.6
  Top Layer w0.178: U1_A2.31@183.457,31.174 183.468,31.185 183.468,31.989 184.183,32.704 184.715,32.704 184.954,32.943 185.163,32.943 185.639,33.42 C157_A2.2@185.639,33.936 185.65,33.947 185.65,35.038 C153_A2.1@185.661,35.049 185.011,35.698 185.011,36.845 182.883,38.974 182.883,66.54 186.159,69.817 R224_A2.2@186.159,69.917
VC17_A1: C145_A1.1 C153_A1.2 R220_A1.2 U1_A1.29 | length 43.7
  Top Layer w0.178: U1_A1.29@79.257,31.124 79.268,31.135 79.268,31.939 79.606,32.276 79.871,32.276 80.11,32.515 80.343,32.515 C145_A1.1@81.69,33.863 81.675,33.878 81.675,34.984 C153_A1.2@81.661,34.999 80.777,35.882 80.777,36.564 78.26,39.08 78.26,64.331 83.696,69.767 R220_A1.2@83.696,69.867
VC17_A2: C145_A2.1 C153_A2.2 R220_A2.2 U1_A2.29 | length 43.7
  Top Layer w0.178: U1_A2.29@184.257,31.174 184.268,31.185 184.268,31.989 184.606,32.326 184.871,32.326 185.11,32.565 185.343,32.565 C145_A2.1@186.69,33.913 186.675,33.928 186.675,35.034 C153_A2.2@186.661,35.049 185.777,35.932 185.777,36.614 183.26,39.13 183.26,64.381 188.696,69.817 R220_A2.2@188.696,69.917
VC18_A1: C137_A1.1 C145_A1.2 R217_A1.2 U1_A1.27 | length 50.7
  Top Layer w0.178: U1_A1.27@80.057,31.124 80.068,31.135 80.068,31.939 80.267,32.137 80.965,32.137 81.79,32.963 ; C137_A1.1@85.433,30.778 83.976,30.778 81.79,32.963 ; R217_A1.2@86.233,69.862 86.233,69.762 85.33,68.859 83.4,68.859 78.638,64.096 78.638,39.237 82.69,35.185 C145_A1.2@82.69,33.863 81.79,32.963
VC18_A2: C137_A2.1 C145_A2.2 R217_A2.2 U1_A2.27 | length 50.7
  Top Layer w0.178: U1_A2.27@185.057,31.174 185.068,31.185 185.068,31.989 185.267,32.187 185.965,32.187 186.79,33.013 ; C137_A2.1@190.433,30.828 188.976,30.828 186.79,33.013 ; R217_A2.2@191.233,69.912 191.233,69.812 190.33,68.909 188.4,68.909 183.638,64.146 183.638,39.287 187.69,35.235 C145_A2.2@187.69,33.913 186.79,33.013
VC19_A1: C131_A1.1 C137_A1.2 R214_A1.2 U1_A1.22 | length 60.5
  Top Layer w0.178: U1_A1.22@82.332,28.049 82.343,28.06 83.199,28.06 84.917,29.778 C137_A1.2@85.433,29.778 85.48,29.731 86.512,29.731 C131_A1.1@86.559,29.683 86.559,31.991 79.016,39.534 79.016,63.94 83.557,68.481 93.54,68.481 94.271,69.212 94.271,69.858 R214_A1.2@94.275,69.862
VC19_A2: C131_A2.1 C137_A2.2 R214_A2.2 U1_A2.22 | length 60.5
  Top Layer w0.178: U1_A2.22@187.332,28.099 187.343,28.11 188.199,28.11 189.917,29.828 C137_A2.2@190.433,29.828 190.48,29.781 191.512,29.781 C131_A2.1@191.559,29.733 191.559,32.041 184.016,39.584 184.016,63.99 188.557,68.531 198.54,68.531 199.271,69.262 199.271,69.908 R214_A2.2@199.275,69.912
VC20_A1: C127_A1.1 C131_A1.2 R208_A1.2 U1_A1.20 | length 63.4
  Top Layer w0.178: U1_A1.20@82.332,27.249 83.384,27.249 84.852,28.717 C127_A1.1@85.441,28.717 85.457,28.7 86.543,28.7 C131_A1.2@86.559,28.683 87.098,29.222 87.098,31.986 79.394,39.691 79.394,63.784 83.713,68.103 95.156,68.103 96.815,69.762 R208_A1.2@96.815,69.862
VC20_A2: C127_A2.1 C131_A2.2 R208_A2.2 U1_A2.20 | length 63.4
  Top Layer w0.178: U1_A2.20@187.332,27.299 188.384,27.299 189.852,28.767 C127_A2.1@190.441,28.767 190.457,28.75 191.543,28.75 C131_A2.2@191.559,28.733 192.098,29.272 192.098,32.036 184.394,39.741 184.394,63.834 188.713,68.153 200.156,68.153 201.815,69.812 R208_A2.2@201.815,69.912
VC21_A1: C121_A1.1 C127_A1.2 R206_A1.2 U1_A1.18 | length 66.6
  Top Layer w0.178: U1_A1.18@82.332,26.449 84.173,26.449 C127_A1.2@85.441,27.717 85.49,27.668 86.51,27.668 C121_A1.1@86.559,27.618 87.476,28.535 87.476,32.143 79.772,39.847 79.772,63.627 83.87,67.725 97.318,67.725 99.355,69.762 R206_A1.2@99.355,69.862
VC21_A2: C121_A2.1 C127_A2.2 R206_A2.2 U1_A2.18 | length 66.6
  Top Layer w0.178: U1_A2.18@187.332,26.499 189.173,26.499 C127_A2.2@190.441,27.767 190.49,27.718 191.51,27.718 C121_A2.1@191.559,27.668 192.476,28.585 192.476,32.193 184.772,39.897 184.772,63.677 188.87,67.775 202.318,67.775 204.355,69.812 R206_A2.2@204.355,69.912
VC22_A1: C117_A1.1 C121_A1.2 R204_A1.2 U1_A1.16 | length 69.7
  Top Layer w0.178: U1_A1.16@82.332,25.649 83.885,25.649 84.283,26.046 84.823,26.046 C117_A1.1@85.446,26.668 85.471,26.643 86.534,26.643 C121_A1.2@86.559,26.618 87.854,27.913 87.854,32.299 80.149,40.004 80.149,63.471 84.026,67.348 99.48,67.348 101.895,69.762 R204_A1.2@101.895,69.862
VC22_A2: C117_A2.1 C121_A2.2 R204_A2.2 U1_A2.16 | length 69.7
  Top Layer w0.178: U1_A2.16@187.332,25.699 188.885,25.699 189.283,26.096 189.823,26.096 C117_A2.1@190.446,26.718 190.471,26.693 191.534,26.693 C121_A2.2@191.559,26.668 192.854,27.963 192.854,32.349 185.149,40.054 185.149,63.521 189.026,67.398 204.48,67.398 206.895,69.812 R204_A2.2@206.895,69.912
VC23_A1: C111_A1.1 C117_A1.2 R202_A1.2 U1_A1.14 | length 72.8
  Top Layer w0.178: U1_A1.14@82.332,24.849 83.711,24.849 84.531,25.668 C117_A1.2@85.446,25.668 86.514,25.668 C111_A1.1@86.559,25.623 88.232,27.296 88.232,32.456 80.527,40.16 80.527,63.314 84.183,66.97 101.642,66.97 104.435,69.762 R202_A1.2@104.435,69.862
VC23_A2: C111_A2.1 C117_A2.2 R202_A2.2 U1_A2.14 | length 72.8
  Top Layer w0.178: U1_A2.14@187.332,24.899 188.711,24.899 189.531,25.718 C117_A2.2@190.446,25.718 191.514,25.718 C111_A2.1@191.559,25.673 193.232,27.346 193.232,32.506 185.527,40.21 185.527,63.364 189.183,67.02 206.642,67.02 209.435,69.812 R202_A2.2@209.435,69.912
VC24_A1: C107_A1.1 C111_A1.2 R200_A1.2 U1_A1.12 | length 75.8
  Top Layer w0.178: U1_A1.12@82.532,24.037 82.546,24.051 84.823,24.051 C107_A1.1@85.446,24.673 85.471,24.648 86.534,24.648 C111_A1.2@86.559,24.623 88.609,26.674 88.609,32.612 80.905,40.317 80.905,63.158 84.339,66.592 102.407,66.592 105.027,69.212 106.425,69.212 106.975,69.762 R200_A1.2@106.975,69.862
VC24_A2: C107_A2.1 C111_A2.2 R200_A2.2 U1_A2.12 | length 75.8
  Top Layer w0.178: U1_A2.12@187.532,24.087 187.546,24.101 189.823,24.101 C107_A2.1@190.446,24.723 190.471,24.698 191.534,24.698 C111_A2.2@191.559,24.673 193.609,26.724 193.609,32.662 185.905,40.367 185.905,63.208 189.339,66.642 207.407,66.642 210.027,69.262 211.425,69.262 211.975,69.812 R200_A2.2@211.975,69.912
VC25_A1: C101_A1.1 C107_A1.2 R198_A1.2 U1_A1.10 | length 79.1
  Top Layer w0.178: U1_A1.10@82.332,23.249 83.908,23.249 84.333,23.673 C107_A1.2@85.446,23.673 85.456,23.663 86.549,23.663 C101_A1.1@86.559,23.653 88.987,26.081 88.987,32.769 81.283,40.473 81.283,63.001 84.496,66.214 104.578,66.214 107.576,69.212 108.965,69.212 109.515,69.762 R198_A1.2@109.515,69.862
VC25_A2: C101_A2.1 C107_A2.2 R198_A2.2 U1_A2.10 | length 79.1
  Top Layer w0.178: U1_A2.10@187.332,23.299 188.908,23.299 189.333,23.723 C107_A2.2@190.446,23.723 190.456,23.713 191.549,23.713 C101_A2.1@191.559,23.703 193.987,26.131 193.987,32.819 186.283,40.523 186.283,63.051 189.496,66.264 209.578,66.264 212.576,69.262 213.965,69.262 214.515,69.812 R198_A2.2@214.515,69.912
VC26_A1: C101_A1.2 C122_A1.1 R195_A1.2 U1_A1.8 | length 82.3
  Top Layer w0.178: U1_A1.8@82.332,22.449 84.575,22.449 84.78,22.653 C122_A1.1@85.441,22.653 ; C122_A1.1@85.441,22.713 85.47,22.683 C101_A1.2@86.589,22.683 ; C101_A1.2@86.559,22.653 86.72,22.815 87.098,23.192 87.098,23.344 88.442,24.688 89.365,25.611 89.365,32.925 81.661,40.63 81.661,62.845 84.652,65.836 106.749,65.836 110.125,69.212 111.505,69.212 112.055,69.762 R195_A1.2@112.055,69.862
VC26_A2: C101_A2.2 C122_A2.1 R195_A2.2 U1_A2.8 | length 82.3
  Top Layer w0.178: U1_A2.8@187.332,22.499 189.575,22.499 189.78,22.703 C122_A2.1@190.441,22.703 ; C122_A2.1@190.441,22.763 190.47,22.733 C101_A2.2@191.589,22.733 ; C101_A2.2@191.559,22.703 191.72,22.865 192.098,23.242 192.098,23.394 193.442,24.738 194.365,25.661 194.365,32.975 186.661,40.68 186.661,62.895 189.652,65.886 211.749,65.886 215.125,69.262 216.505,69.262 217.055,69.812 R195_A2.2@217.055,69.912
VIO_3.3V_A1: C158_A1.2 C160_A1.1 J6_A1.3 J7_A1.6 R70_A1.2 U4_A1.1 U5_A1.1 | length 36.8
  Top Layer w0.305: v2(60.425,11.963) 60.425,11.975 60.608,12.157 U5_A1.1@61.637,12.157
  Bottom Layer w0.178: 57.566,19.252 57.613,19.299
  Bottom Layer w0.305: J6_A1.3@47.323,10.421 51.96,10.421 52.165,10.626 ; v2(53.3,13.898) 52.509,13.898 52.165,13.553 52.165,10.626 ; 57.566,19.252 57.555,19.241 57.555,17.954 58.229,17.28 58.756,17.28 59.366,16.669 59.366,15.014 60.425,13.955 v2(60.425,11.963) 60.425,10.768 60.321,10.664 56.822,10.664 56.784,10.626 52.165,10.626 ; 57.613,19.299 57.697,19.383 57.697,21.865 58.35,22.517 U4_A1.1@58.35,22.917 ; U4_A1.1@58.35,22.717 U4_A1.1@58.35,22.917 ; R70_A1.2@59.893,25.4 R70_A1.2@59.887,25.406 59.887,25.306 59.676,25.095 59.035,25.095 58.704,24.764 58.585,24.764 58.349,24.528 58.349,24.438 58.171,24.259 58.149,24.259 58.102,24.212 C158_A1.2@58.102,24.162 58.063,24.123 58.063,23.204 U4_A1.1@58.35,22.917
VIO_3.3V_A2: C158_A2.2 C160_A2.1 J6_A2.3 J7_A2.6 R70_A2.2 U4_A2.1 U5_A2.1 | length 46.7
  Top Layer w0.178: v2(158.3,13.948) 158.503,14.151 J7_A2.6@158.86,14.151
  Top Layer w0.305: v2(165.425,12.013) 165.425,12.025 165.608,12.207 U5_A2.1@166.637,12.207
  Mid Layer 1 w0.178: J6_A2.3@152.323,10.471 152.576,10.218 153.057,10.218 153.088,10.187 157.637,10.187 157.742,10.291 157.742,13.389 v2(158.3,13.948)
  Bottom Layer w0.178: 162.597,19.4 162.642,19.356 ; 162.703,17.934 162.703,17.856 162.748,17.811
  Bottom Layer w0.305: J6_A2.3@152.323,10.471 156.96,10.471 157.165,10.676 ; v2(158.3,13.948) 157.509,13.948 157.165,13.603 157.165,10.676 ; 162.703,17.934 162.503,18.134 162.503,18.868 162.66,19.025 162.66,19.4 162.66,21.44 163.265,22.045 163.265,22.882 163.35,22.967 163.102,23.215 163.102,24.262 163.149,24.309 163.171,24.309 163.349,24.488 163.349,24.578 163.585,24.814 163.704,24.814 164.035,25.145 164.676,25.145 164.887,25.356 R70_A2.2@164.887,25.456 R70_A2.2@164.893,25.45 ; 162.748,17.811 163.229,17.33 163.756,17.33 164.366,16.719 164.366,15.064 165.425,14.005 v2(165.425,12.013) 165.425,10.818 165.321,10.714 161.822,10.714 161.784,10.676 157.165,10.676
VIO_A1: C29_A1.2 J6_A1.2 J12_A1.1 Q1_A1.4 R155_A1.2 R166_A1.2 R167_A1.2 R233_A1.2 R234_A1.2 R235_A1.2 U1_A1.87 | length 122.1
  Top Layer w0.178: R234_A1.2@32.668,17.664 32.493,17.839 31.458,17.839 R235_A1.2@31.283,17.664 31.108,17.839 30.058,17.839 R233_A1.2@29.883,17.664 29.316,17.664 29.212,17.559 ; J12_A1.1@33.171,27.196 33.171,28.221 32.512,28.88 30.171,28.88 28.449,27.158 28.449,18.322 29.212,17.559 ; J6_A1.2@47.323,12.961 48.73,12.961 48.957,12.734 49.854,12.734 R155_A1.2@50.065,12.523 ; v2(74.029,6.375) 74.029,6.339 v2@74.091,6.277 ; U1_A1.87@75.257,17.774 75.257,16.83 74.611,16.184 74.398,16.184 73.462,15.249 72.873,15.249 72.608,15.248 72.23,14.871 71.525,14.871 71.475,14.821 71.351,14.821 C29_A1.2@71.19,14.66 70.651,14.121 70.651,13.29 70.701,13.24 70.701,12.368 71.668,11.401 73.738,11.401 74.195,10.945 74.195,6.381 v2@74.091,6.277 ; v2(76.262,6.055) 76.308,6.01 76.892,6.01 Q1_A1.4@76.937,5.965 ; 29.212,17.559 28.925,17.272 28.576,17.272 28.279,16.975 28.279,11.335 34.793,4.821 71.812,4.821 73.268,6.277 v2@74.091,6.277
  Mid Layer 1 w0.178: v2(47.256,4.638) 45.906,5.988 45.906,11.544 J6_A1.2@47.323,12.961
  Bottom Layer w0.178: J6_A1.2@47.323,12.961 48.682,14.32 48.682,15.088 49.788,16.194 52.957,16.194 53.048,16.103 55.849,16.103 ; R167_A1.2@55.83,15.371 55.83,16.085 55.849,16.103 ; R166_A1.2@57.11,16.627 R166_A1.2@57.01,16.627 56.91,16.627 56.386,16.103 55.849,16.103 ; v2(74.029,6.375) 74.04,6.364 74.04,6.101 74.268,5.872 76.012,5.872 76.195,6.055 v2(76.262,6.055)
VIO_A2: C29_A2.2 J6_A2.2 J12_A2.1 Q1_A2.4 R155_A2.2 R166_A2.2 R167_A2.2 R233_A2.2 R234_A2.2 R235_A2.2 U1_A2.87 | length 122.3
  Top Layer w0.178: R234_A2.2@137.668,17.714 137.493,17.889 136.458,17.889 R235_A2.2@136.283,17.714 ; J12_A2.1@138.171,27.246 138.171,27.715 138.171,28.271 137.512,28.93 135.171,28.93 133.449,27.208 133.449,18.372 134.212,17.609 ; J6_A2.2@152.323,13.011 153.73,13.011 153.957,12.784 154.854,12.784 R155_A2.2@155.065,12.573 ; v2(179.029,6.425) 179.029,6.389 v2@179.091,6.327 ; U1_A2.87@180.257,17.824 180.257,16.88 179.611,16.234 179.398,16.234 178.462,15.299 177.873,15.299 177.608,15.298 177.23,14.921 176.525,14.921 176.475,14.871 176.351,14.871 C29_A2.2@176.19,14.71 175.651,14.171 175.651,13.34 175.701,13.29 175.701,12.418 176.668,11.451 178.738,11.451 179.195,10.995 179.195,6.431 v2@179.091,6.327 ; v2(181.262,6.105) 181.308,6.06 181.892,6.06 Q1_A2.4@181.937,6.015 ; 134.212,17.609 134.316,17.714 R233_A2.2@134.883,17.714 135.058,17.889 R235_A2.2@136.108,17.889 ; 134.212,17.609 133.925,17.322 133.576,17.322 133.279,17.025 133.279,11.385 139.793,4.871 176.812,4.871 178.268,6.327 v2@179.091,6.327 ; R235_A2.2@136.108,17.889 R235_A2.2@136.283,17.714 ; R235_A2.2@136.108,17.889 R235_A2.2@136.283,17.714 ; R235_A2.2@136.108,17.889 R235_A2.2@136.283,17.714
  Mid Layer 1 w0.178: v2(152.256,4.688) 150.906,6.038 150.906,11.594 J6_A2.2@152.323,13.011
  Bottom Layer w0.178: J6_A2.2@152.323,13.011 153.682,14.37 153.682,15.138 154.788,16.244 157.957,16.244 158.048,16.153 160.849,16.153 161.386,16.153 R166_A2.2@161.91,16.677 ; R167_A2.2@160.83,15.421 160.83,16.135 ; v2(179.029,6.425) 179.04,6.414 179.04,6.151 179.268,5.922 181.012,5.922 181.195,6.105 v2(181.262,6.105)
pads on no net: FID1.1 FID2.1 FID3.1 H1.1 H2.1 H3.1 H4.1 J1.3 J1.4 J1.MH1 J1.MH2 J2.1 J2.2 J2.MH1 J2.MH2 J4_A1.6 J4_A1.7 J4_A1.8 J4_A1.9 J4_A1.17 J4_A1.18 J4_A1.19 J4_A1.20 J4_A1.25 J4_A1.26 J4_A1.27 J4_A1.28 J4_A1.29 J4_A1.38 J4_A1.39 J4_A1.40 J4_A1.41 J4_A1.42 J4_A2.6 J4_A2.7 J4_A2.8 J4_A2.9 J4_A2.17 J4_A2.18 J4_A2.19 J4_A2.20 J4_A2.25 J4_A2.26 J4_A2.27 J4_A2.28 J4_A2.29 J4_A2.38 J4_A2.39 J4_A2.40 J4_A2.41 J4_A2.42 J5_A1.6 J5_A1.7 J5_A1.8 J5_A1.9 J5_A1.18 J5_A1.19 J5_A1.20 J5_A1.26 J5_A1.27 J5_A1.28 J5_A1.29 J5_A1.30 J5_A1.37 J5_A1.38 J5_A1.39 J5_A1.40 J5_A1.41 J5_A1.42 J5_A2.6 J5_A2.7 J5_A2.8 J5_A2.9 J5_A2.18 J5_A2.19 J5_A2.20 J5_A2.26 J5_A2.27 J5_A2.28 J5_A2.29 J5_A2.30 J5_A2.37 J5_A2.38 J5_A2.39 J5_A2.40 J5_A2.41 J5_A2.42 J7_A1.2 J7_A2.2 LBL1.0 T1.2 T3.2 U1_A1.1 U1_A1.2 U1_A1.3 U1_A1.4 U1_A1.24 U1_A1.25 U1_A1.26 U1_A1.98 U1_A2.1 U1_A2.2 U1_A2.3 U1_A2.4 U1_A2.24 U1_A2.25 U1_A2.26 U1_A2.98 U2_A1.7 U2_A2.7 U3_A1.7 U3_A2.7 U4_A1.4 U4_A2.4

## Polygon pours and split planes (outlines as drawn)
GND_A1 on Mid Layer 2 "MID_LAYER_2_GND_A1_P004" (solid, remove dead copper, pour order 53): 2.942,97.496 2.942,30.687 2.942,2.524 5.805,-0.338 119.742,-0.338 121.392,1.312 121.392,97.437
GND_A2 on Mid Layer 2 "Mid Layer 2-GND_A2" (solid, remove dead copper, pour order 58): 107.942,2.574 110.805,-0.288 224.742,-0.288 225.558,0.527 239.377,0.527 240.2,1.35 240.2,24.2 240.2,97.48 125.492,97.537 125.492,31.733 124.496,30.737 107.942,30.737
GND_A2 on Top Layer "Top Layer-GND_A2" (solid, remove dead copper, pour order 57): 107.849,2.465 110.711,-0.397 224.649,-0.397 225.464,0.418 239.284,0.418 240.984,2.118 240.984,97.37 125.399,97.428 125.399,31.624 124.403,30.628 107.849,30.628
GND_A1 on Top Layer "TOP_LAYER_GND_A1_P047" (solid, remove dead copper, pour order 47): 2.831,97.763 2.831,30.954 2.831,2.791 5.693,-0.071 119.631,-0.071 121.281,1.579 121.281,97.704
GND_A1 on Bottom Layer "BOTTOM_LAYER_GND_A1_P051" (solid, remove dead copper, pour order 51): 2.942,97.496 2.942,30.687 2.942,2.524 5.805,-0.338 119.742,-0.338 121.392,1.312 121.392,97.437
GND_A2 on Bottom Layer "Bottom Layer-GND_A2" (solid, remove dead copper, pour order 56): 108.037,2.471 110.899,-0.391 224.837,-0.391 225.652,0.424 239.472,0.424 240.294,1.247 240.294,24.097 240.294,97.377 125.587,97.434 125.587,31.63 124.591,30.634 108.037,30.634
GND_A1 on Mid Layer 1 "MID_LAYER_1_GND_A1_P049" (solid, remove dead copper, pour order 49): 2.942,97.496 2.942,30.687 2.942,2.524 5.805,-0.338 119.742,-0.338 121.392,1.312 121.392,97.437
GND_A2 on Mid Layer 1 "Mid Layer 1-GND_A2" (solid, remove dead copper, pour order 55): 107.942,2.574 110.805,-0.288 224.742,-0.288 225.558,0.527 239.377,0.527 240.984,2.134 240.984,97.48 125.492,97.537 125.492,31.733 124.496,30.737 107.942,30.737

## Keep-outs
Keep-Out Layer:
  text ".Layer_Name" at 14.656,-21.806 h1.52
